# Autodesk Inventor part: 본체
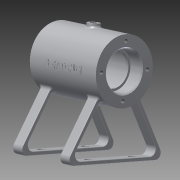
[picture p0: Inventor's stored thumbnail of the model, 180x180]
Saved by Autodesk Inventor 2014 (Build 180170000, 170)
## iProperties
Created: 2016-03
Part Number: 본체
Material: 알루미늄 6061
Document SubType Name: Modeling
Designer: 703-15
Density: 2.71 g/cm^3
Appearance: 알루미늄 - 평지
Mass: 254.955 g
Surface Area: 325.404 cm^2
Volume: 94.0795 cm^3
Author: 703-15
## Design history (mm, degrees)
sketch "스케치1"
  geometry: L1 (-15.556, 65)-(15.556, 65); L2 (-35, 91)-(35, 91); L3 (35, 91)-(35, 81); L4 (35, 81)-(23, 81); L5 (23, 81)-(23, 79); L6 (23, 79)-(21.091, 79); L7 (21.091, 79)-(21.091, 83.206); L8 (21.091, 83.206)-(-20.909, 83.206); L9 (-20.909, 83.206)-(-20.909, 79); L10 (-20.909, 79)-(-23, 79); L11 (-23, 79)-(-23, 81); L12 (-23, 81)-(-35, 81); L13 (-35, 81)-(-35, 91); 3 further points
  constraints: 26 end point, 7 parallel, 4 perpendicular, 2 midpoint, 2 vertical alignment, 1 collinear, 1 horizontal
  dimensions: "d0" = 65 distance from line of point (0, 0) L1; "d1" = 70 distance of L2.start L2.end; "d2" = 52 diameter of L2 L1; "d3" = 32 diameter of L4 L1; "d4" = 28 diameter of L6 L1; "d5" = 28 diameter of L10 L1; "d6" = 32 diameter of L12 L1; "d7" = 12 distance of L3.end L4.end; "d8" = 42 distance of L7.end L8.end; "d9" = 12 distance of L11.end L12.end
revolve "회전1" sketch "스케치1" stored, may be unused: angle "d10" = 90 deg
node "작업 평면2"
  node "작업 평면1"
sketch "스케치2"
  geometry: L1 (-18.235, 18.534)-(-65, 45.534); L2 (-65, 45.534)-(-65, -45.534); L3 (-65, -45.534)-(-18.235, -18.534); L4 (0, 0)-(-67.936, 0); L5 (-20.291, 16.257)-(-62, 40.338); L6 (-62, 40.338)-(-62, -40.338); L7 (-62, -40.338)-(-20.291, -16.257); A1 r 26 centre (0, 0) between (-18.235, 18.534) and (-18.235, -18.534) reference; 2 further points
  constraints: 14 end point, 4 point on circle, 2 coincident, 1 midpoint, 1 perpendicular, 1 vertical, 2 other
  dimensions: "d12" = 30 deg angle of L4 L3; "d13" = 30 deg angle of L4 L1; "d14" = 3 distance between parallel lines of L1 L5
extrude "돌출1" join sketch "스케치2" distance "d15" = 10; taper "d16" = 0 deg
fillet "모깎기1" dims "d17" = 5
sketch "스케치3"
  geometry: L1 (0, -5.196)-(10, -5.196) reference; L2 (0, -5.196)-(0, 68.551) reference; L3 (10, 68.551)-(0, 68.551) reference; L4 (10, -5.196)-(10, 68.551) reference; 3 further points
  dimensions: "d18" = 20 vertical distance of point (5, 11.677) point (-20, 31.677); "d19" = 40 distance of point (5, 51.677) point (5, 11.677)
hole "구멍1" sketch "스케치3" at (5, 11.677), (5, 51.677) diameter "d20" = 6; stored, may be unused: countersink angle "d24" = 90 deg, drill point angle "d26" = 118 deg; dims "d21" = 6, "d22" = 4, "d23" = 2, "d25" = 8
node "작업 평면4"
  node "작업 평면3"
sketch "스케치4"
  geometry: C1 r 5 at (0, 0); 1 further point
  constraints: 1 centre point, 1 coincident
  dimensions: "d28" = 10 diameter of C1
extrude "돌출2" join sketch "스케치4" distance "d29" = 5; taper "d30" = 0 deg
sketch "스케치5"
  geometry: C1 r 5 at (0, 0) reference; 1 further point
  constraints: 1 coincident
hole "구멍2" sketch "스케치5" at (0, 0) diameter "d31" = 5.188; stored, may be unused: countersink angle "d35" = 90 deg, drill point angle "d37" = 0 deg; dims "d32" = 20, "d33" = 4, "d34" = 2, "d36" = 20
sketch "스케치6"
  geometry: C1 r 2.594 at (0, 0) reference; C2 r 5 at (0, 0) reference; C3 r 6 at (0, 0); 1 further point
  constraints: 1 centre point, 1 coincident
  dimensions: "d41" = 12 diameter of C3
extrude "돌출3" join sketch "스케치6" distance "d42" = 5; taper "d43" = 0 deg
sketch "스케치7"
  geometry: C1 r 26 at (0, 0) reference; 2 further points
  constraints: 1 vertical alignment
  dimensions: "d44" = 21 distance of C1.centre point (0, 21)
hole "구멍3" sketch "스케치7" at (0, 21) diameter "d45" = 3.242; stored, may be unused: countersink angle "d49" = 90 deg, drill point angle "d51" = 118 deg; dims "d46" = 8, "d47" = 4, "d48" = 2, "d50" = 10
node "작업 평면6"
sketch "스케치8"
  geometry: L1 (35, 26)-(-35, 26) reference; L2 (-35, 26)-(-35, -26) reference; 2 further points
  constraints: 1 other
  dimensions: "d55" = 35 distance from line of L2 point (0, 0); "d56" = 26 distance from line of L1 point (0, 0)
feature "엠보싱1" sketch "스케치8" dims "d57" = 0.5, "d58" = 0
chamfer "모따기1" distance "d59" = 1; stored, may be unused: second distance "d60" = 2, angle "d61" = 45 deg
fillet "모깎기2" dims "d62" = 3
fillet "모깎기3" dims "d63" = 0.3
fillet "모깎기4" dims "d64" = 0.5
fillet "모깎기5" dims "d65" = 0.5
fillet "모깎기6" dims "d66" = 2
fillet "모깎기7" dims "d67" = 3
node "솔리드1"
mirror "대칭1"
pattern_circular "원형 패턴1" dims angle "d39" = 165 deg
pattern_circular "원형 패턴2" dims angle "d53" = 360 deg
mirror "대칭2"
node "투영된 루프1"
node "작업 평면5"
other parameters: "d27" = 3
